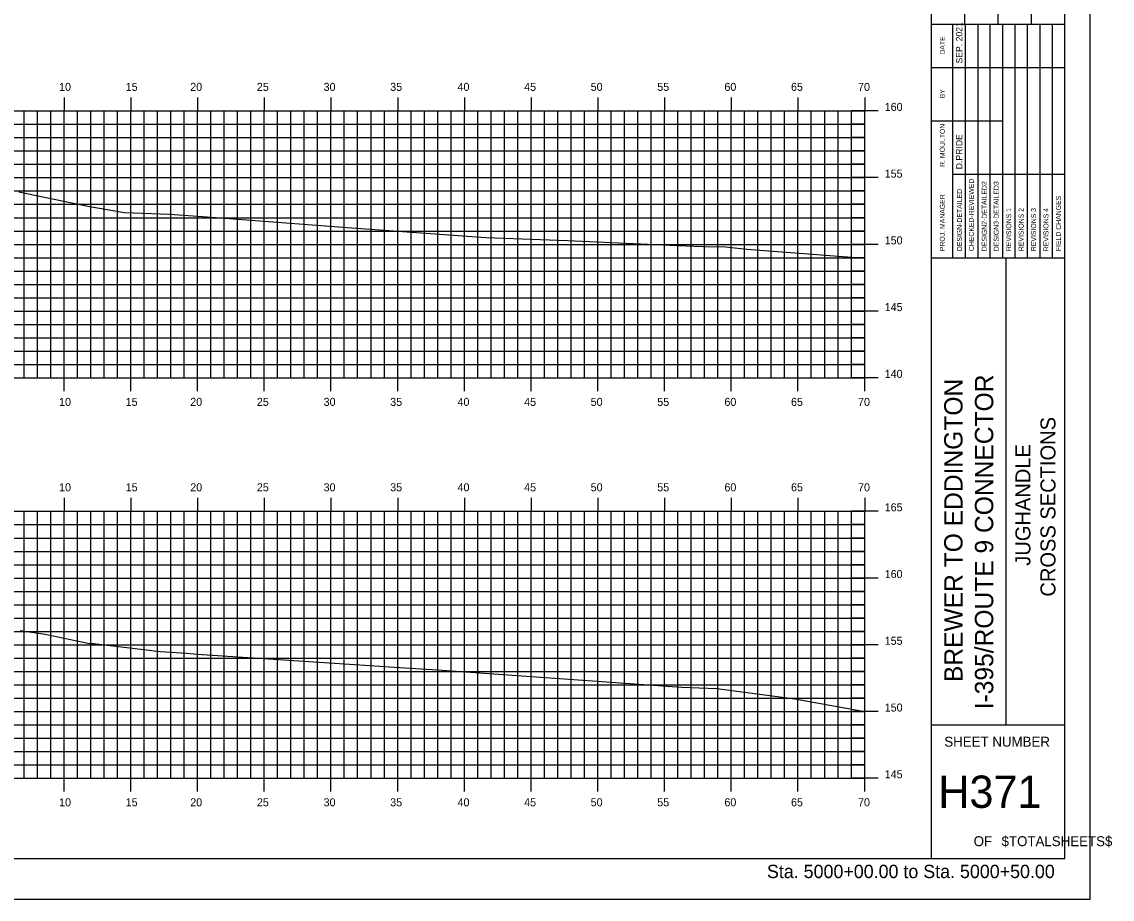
# Model space of a CAD drawing. Extents: x 850752 to 850923, y 365876 to 365986.
# Drawn here: x 850841.5 to 850923.2, y 365875.8 to 365941.5 of the extents above; entities that cross this region are included whole.
import ezdxf

# ---------------------------------------------------------------- set-up
doc = ezdxf.new("R2010")
doc.units = 0
for name, color, linetype in [('BORDER', 7, 'Continuous'), ('H_V ANNOTATION', 7, 'Continuous'), ('MAJOR', 7, 'Continuous'), ('MINOR', 7, 'Continuous'), ('PLOT BOUNDARY', 7, 'Continuous'), ('S_Roadway_Centerline', 7, 'Continuous')]:
    doc.layers.add(name, color=color, linetype=linetype)

msp = doc.modelspace()

# ---------------------------------------------------------------- linework, layer by layer
at = {"layer": 'BORDER'}
for p, q in [((850909.629, 365878.833), (850909.629, 365983.833)), ((850912.129, 365941.336), (850912.129, 365949.984)), ((850914.629, 365941.336), (850914.629, 365949.984)), ((850917.129, 365941.336), (850917.129, 365949.984)), ((850909.629, 365941.336), (850919.629, 365941.336)), ((850909.629, 365923.836), (850919.629, 365923.836)), ((850915.22, 365888.836), (850915.22, 365923.836)), ((850909.629, 365888.836), (850919.629, 365888.836))]:
    msp.add_line(p, q, dxfattribs=at)
msp.add_lwpolyline([(850759.629, 365878.833), (850919.629, 365878.833), (850919.629, 365983.833), (850759.629, 365983.833)], close=True, dxfattribs=at)
for points in [[(850911.244, 365938.086), (850911.244, 365941.336)], [(850912.176, 365923.839), (850912.176, 365941.336)], [(850913.108, 365941.336), (850913.108, 365923.839)], [(850914.04, 365923.839), (850914.04, 365941.336)], [(850914.971, 365923.839), (850914.971, 365941.336)], [(850915.903, 365923.839), (850915.903, 365941.336)], [(850916.835, 365923.839), (850916.835, 365941.336)], [(850917.767, 365923.839), (850917.767, 365941.336)], [(850918.698, 365923.839), (850918.698, 365941.336)], [(850911.245, 365923.839), (850911.245, 365940.63)], [(850909.629, 365938.086), (850919.629, 365938.086)], [(850909.629, 365934.086), (850911.245, 365934.086)], [(850911.244, 365934.086), (850914.971, 365934.086)], [(850911.244, 365930.086), (850919.629, 365930.086)]]:
    msp.add_lwpolyline(points, dxfattribs=at)
at = {"layer": 'MAJOR'}
for p, q in [((850844.629, 365935.835), (850844.629, 365934.833)), ((850849.629, 365935.835), (850849.629, 365934.833)), ((850854.629, 365935.835), (850854.629, 365934.833)), ((850859.629, 365935.835), (850859.629, 365934.833)), ((850864.629, 365935.835), (850864.629, 365934.833)), ((850869.629, 365935.835), (850869.629, 365934.833)), ((850874.629, 365935.835), (850874.629, 365934.833)), ((850879.629, 365935.835), (850879.629, 365934.833)), ((850884.629, 365935.835), (850884.629, 365934.833)), ((850889.629, 365935.835), (850889.629, 365934.833)), ((850894.629, 365935.835), (850894.629, 365934.833)), ((850899.629, 365935.835), (850899.629, 365934.833)), ((850904.629, 365935.835), (850904.629, 365934.833)), ((850764.629, 365934.833), (850904.629, 365934.833)), ((850764.629, 365934.833), (850904.629, 365934.833)), ((850844.629, 365914.833), (850844.629, 365934.833)), ((850849.629, 365914.833), (850849.629, 365934.833)), ((850854.629, 365914.833), (850854.629, 365934.833)), ((850859.629, 365914.833), (850859.629, 365934.833)), ((850864.629, 365914.833), (850864.629, 365934.833)), ((850869.629, 365914.833), (850869.629, 365934.833)), ((850874.629, 365914.833), (850874.629, 365934.833)), ((850879.629, 365914.833), (850879.629, 365934.833)), ((850884.629, 365914.833), (850884.629, 365934.833)), ((850889.629, 365914.833), (850889.629, 365934.833)), ((850894.629, 365914.833), (850894.629, 365934.833)), ((850899.629, 365914.833), (850899.629, 365934.833)), ((850905.631, 365934.833), (850903.627, 365934.833)), ((850904.629, 365914.833), (850904.629, 365934.833)), ((850904.629, 365914.833), (850904.629, 365934.833)), ((850764.629, 365929.833), (850904.629, 365929.833)), ((850905.631, 365929.833), (850903.627, 365929.833)), ((850764.629, 365924.833), (850904.629, 365924.833)), ((850905.631, 365924.833), (850903.627, 365924.833)), ((850764.629, 365919.833), (850904.629, 365919.833)), ((850905.631, 365919.833), (850903.627, 365919.833)), ((850764.629, 365914.833), (850904.629, 365914.833)), ((850764.629, 365914.833), (850904.629, 365914.833)), ((850844.629, 365913.831), (850844.629, 365914.833)), ((850849.629, 365913.831), (850849.629, 365914.833)), ((850854.629, 365913.831), (850854.629, 365914.833)), ((850859.629, 365913.831), (850859.629, 365914.833)), ((850864.629, 365913.831), (850864.629, 365914.833)), ((850869.629, 365913.831), (850869.629, 365914.833)), ((850874.629, 365913.831), (850874.629, 365914.833)), ((850879.629, 365913.831), (850879.629, 365914.833)), ((850884.629, 365913.831), (850884.629, 365914.833)), ((850889.629, 365913.831), (850889.629, 365914.833)), ((850894.629, 365913.831), (850894.629, 365914.833)), ((850899.629, 365913.831), (850899.629, 365914.833)), ((850905.631, 365914.833), (850903.627, 365914.833)), ((850904.629, 365913.831), (850904.629, 365914.833)), ((850844.629, 365905.835), (850844.629, 365904.833)), ((850849.629, 365905.835), (850849.629, 365904.833)), ((850854.629, 365905.835), (850854.629, 365904.833)), ((850859.629, 365905.835), (850859.629, 365904.833)), ((850864.629, 365905.835), (850864.629, 365904.833)), ((850869.629, 365905.835), (850869.629, 365904.833)), ((850874.629, 365905.835), (850874.629, 365904.833)), ((850879.629, 365905.835), (850879.629, 365904.833)), ((850884.629, 365905.835), (850884.629, 365904.833)), ((850889.629, 365905.835), (850889.629, 365904.833)), ((850894.629, 365905.835), (850894.629, 365904.833)), ((850899.629, 365905.835), (850899.629, 365904.833)), ((850904.629, 365905.835), (850904.629, 365904.833)), ((850764.629, 365904.833), (850904.629, 365904.833)), ((850764.629, 365904.833), (850904.629, 365904.833)), ((850844.629, 365884.833), (850844.629, 365904.833)), ((850849.629, 365884.833), (850849.629, 365904.833)), ((850854.629, 365884.833), (850854.629, 365904.833)), ((850859.629, 365884.833), (850859.629, 365904.833)), ((850864.629, 365884.833), (850864.629, 365904.833)), ((850869.629, 365884.833), (850869.629, 365904.833)), ((850874.629, 365884.833), (850874.629, 365904.833)), ((850879.629, 365884.833), (850879.629, 365904.833)), ((850884.629, 365884.833), (850884.629, 365904.833)), ((850889.629, 365884.833), (850889.629, 365904.833)), ((850894.629, 365884.833), (850894.629, 365904.833)), ((850899.629, 365884.833), (850899.629, 365904.833)), ((850905.631, 365904.833), (850903.627, 365904.833)), ((850904.629, 365884.833), (850904.629, 365904.833)), ((850904.629, 365884.833), (850904.629, 365904.833)), ((850764.629, 365899.833), (850904.629, 365899.833)), ((850905.631, 365899.833), (850903.627, 365899.833)), ((850764.629, 365894.833), (850904.629, 365894.833)), ((850905.631, 365894.833), (850903.627, 365894.833)), ((850764.629, 365889.833), (850904.629, 365889.833)), ((850905.631, 365889.833), (850903.627, 365889.833)), ((850764.629, 365884.833), (850904.629, 365884.833)), ((850764.629, 365884.833), (850904.629, 365884.833)), ((850844.629, 365883.831), (850844.629, 365884.833)), ((850849.629, 365883.831), (850849.629, 365884.833)), ((850854.629, 365883.831), (850854.629, 365884.833)), ((850859.629, 365883.831), (850859.629, 365884.833)), ((850864.629, 365883.831), (850864.629, 365884.833)), ((850869.629, 365883.831), (850869.629, 365884.833)), ((850874.629, 365883.831), (850874.629, 365884.833)), ((850879.629, 365883.831), (850879.629, 365884.833)), ((850884.629, 365883.831), (850884.629, 365884.833)), ((850889.629, 365883.831), (850889.629, 365884.833)), ((850894.629, 365883.831), (850894.629, 365884.833)), ((850899.629, 365883.831), (850899.629, 365884.833)), ((850905.631, 365884.833), (850903.627, 365884.833)), ((850904.629, 365883.831), (850904.629, 365884.833))]:
    msp.add_line(p, q, dxfattribs=at)
at = {"layer": 'MINOR'}
for p, q in [((850841.629, 365914.833), (850841.629, 365934.833)), ((850842.629, 365914.833), (850842.629, 365934.833)), ((850843.629, 365914.833), (850843.629, 365934.833)), ((850845.629, 365914.833), (850845.629, 365934.833)), ((850846.629, 365914.833), (850846.629, 365934.833)), ((850847.629, 365914.833), (850847.629, 365934.833)), ((850848.629, 365914.833), (850848.629, 365934.833)), ((850850.629, 365914.833), (850850.629, 365934.833)), ((850851.629, 365914.833), (850851.629, 365934.833)), ((850852.629, 365914.833), (850852.629, 365934.833)), ((850853.629, 365914.833), (850853.629, 365934.833)), ((850855.629, 365914.833), (850855.629, 365934.833)), ((850856.629, 365914.833), (850856.629, 365934.833)), ((850857.629, 365914.833), (850857.629, 365934.833)), ((850858.629, 365914.833), (850858.629, 365934.833)), ((850860.629, 365914.833), (850860.629, 365934.833)), ((850861.629, 365914.833), (850861.629, 365934.833)), ((850862.629, 365914.833), (850862.629, 365934.833)), ((850863.629, 365914.833), (850863.629, 365934.833)), ((850865.629, 365914.833), (850865.629, 365934.833)), ((850866.629, 365914.833), (850866.629, 365934.833)), ((850867.629, 365914.833), (850867.629, 365934.833)), ((850868.629, 365914.833), (850868.629, 365934.833)), ((850870.629, 365914.833), (850870.629, 365934.833)), ((850871.629, 365914.833), (850871.629, 365934.833)), ((850872.629, 365914.833), (850872.629, 365934.833)), ((850873.629, 365914.833), (850873.629, 365934.833)), ((850875.629, 365914.833), (850875.629, 365934.833)), ((850876.629, 365914.833), (850876.629, 365934.833)), ((850877.629, 365914.833), (850877.629, 365934.833)), ((850878.629, 365914.833), (850878.629, 365934.833)), ((850880.629, 365914.833), (850880.629, 365934.833)), ((850881.629, 365914.833), (850881.629, 365934.833)), ((850882.629, 365914.833), (850882.629, 365934.833)), ((850883.629, 365914.833), (850883.629, 365934.833)), ((850885.629, 365914.833), (850885.629, 365934.833)), ((850886.629, 365914.833), (850886.629, 365934.833)), ((850887.629, 365914.833), (850887.629, 365934.833)), ((850888.629, 365914.833), (850888.629, 365934.833)), ((850890.629, 365914.833), (850890.629, 365934.833)), ((850891.629, 365914.833), (850891.629, 365934.833)), ((850892.629, 365914.833), (850892.629, 365934.833)), ((850893.629, 365914.833), (850893.629, 365934.833)), ((850895.629, 365914.833), (850895.629, 365934.833)), ((850896.629, 365914.833), (850896.629, 365934.833)), ((850897.629, 365914.833), (850897.629, 365934.833)), ((850898.629, 365914.833), (850898.629, 365934.833)), ((850900.629, 365914.833), (850900.629, 365934.833)), ((850901.629, 365914.833), (850901.629, 365934.833)), ((850902.629, 365914.833), (850902.629, 365934.833)), ((850903.629, 365914.833), (850903.629, 365934.833)), ((850764.629, 365933.833), (850904.629, 365933.833)), ((850904.629, 365933.833), (850903.627, 365933.833)), ((850764.629, 365932.833), (850904.629, 365932.833)), ((850904.629, 365932.833), (850903.627, 365932.833)), ((850764.629, 365931.833), (850904.629, 365931.833)), ((850904.629, 365931.833), (850903.627, 365931.833)), ((850764.629, 365930.833), (850904.629, 365930.833)), ((850904.629, 365930.833), (850903.627, 365930.833)), ((850764.629, 365928.833), (850904.629, 365928.833)), ((850904.629, 365928.833), (850903.627, 365928.833)), ((850764.629, 365927.833), (850904.629, 365927.833)), ((850904.629, 365927.833), (850903.627, 365927.833)), ((850764.629, 365926.833), (850904.629, 365926.833)), ((850904.629, 365926.833), (850903.627, 365926.833)), ((850764.629, 365925.833), (850904.629, 365925.833)), ((850904.629, 365925.833), (850903.627, 365925.833)), ((850764.629, 365923.833), (850904.629, 365923.833)), ((850904.629, 365923.833), (850903.627, 365923.833)), ((850764.629, 365922.833), (850904.629, 365922.833)), ((850904.629, 365922.833), (850903.627, 365922.833)), ((850764.629, 365921.833), (850904.629, 365921.833)), ((850904.629, 365921.833), (850903.627, 365921.833)), ((850764.629, 365920.833), (850904.629, 365920.833)), ((850904.629, 365920.833), (850903.627, 365920.833)), ((850764.629, 365918.833), (850904.629, 365918.833)), ((850904.629, 365918.833), (850903.627, 365918.833)), ((850764.629, 365917.833), (850904.629, 365917.833)), ((850904.629, 365917.833), (850903.627, 365917.833)), ((850764.629, 365916.833), (850904.629, 365916.833)), ((850904.629, 365916.833), (850903.627, 365916.833)), ((850764.629, 365915.833), (850904.629, 365915.833)), ((850904.629, 365915.833), (850903.627, 365915.833)), ((850841.629, 365884.833), (850841.629, 365904.833)), ((850842.629, 365884.833), (850842.629, 365904.833)), ((850843.629, 365884.833), (850843.629, 365904.833)), ((850845.629, 365884.833), (850845.629, 365904.833)), ((850846.629, 365884.833), (850846.629, 365904.833)), ((850847.629, 365884.833), (850847.629, 365904.833)), ((850848.629, 365884.833), (850848.629, 365904.833)), ((850850.629, 365884.833), (850850.629, 365904.833)), ((850851.629, 365884.833), (850851.629, 365904.833)), ((850852.629, 365884.833), (850852.629, 365904.833)), ((850853.629, 365884.833), (850853.629, 365904.833)), ((850855.629, 365884.833), (850855.629, 365904.833)), ((850856.629, 365884.833), (850856.629, 365904.833)), ((850857.629, 365884.833), (850857.629, 365904.833)), ((850858.629, 365884.833), (850858.629, 365904.833)), ((850860.629, 365884.833), (850860.629, 365904.833)), ((850861.629, 365884.833), (850861.629, 365904.833)), ((850862.629, 365884.833), (850862.629, 365904.833)), ((850863.629, 365884.833), (850863.629, 365904.833)), ((850865.629, 365884.833), (850865.629, 365904.833)), ((850866.629, 365884.833), (850866.629, 365904.833)), ((850867.629, 365884.833), (850867.629, 365904.833)), ((850868.629, 365884.833), (850868.629, 365904.833)), ((850870.629, 365884.833), (850870.629, 365904.833)), ((850871.629, 365884.833), (850871.629, 365904.833)), ((850872.629, 365884.833), (850872.629, 365904.833)), ((850873.629, 365884.833), (850873.629, 365904.833)), ((850875.629, 365884.833), (850875.629, 365904.833)), ((850876.629, 365884.833), (850876.629, 365904.833)), ((850877.629, 365884.833), (850877.629, 365904.833)), ((850878.629, 365884.833), (850878.629, 365904.833)), ((850880.629, 365884.833), (850880.629, 365904.833)), ((850881.629, 365884.833), (850881.629, 365904.833)), ((850882.629, 365884.833), (850882.629, 365904.833)), ((850883.629, 365884.833), (850883.629, 365904.833)), ((850885.629, 365884.833), (850885.629, 365904.833)), ((850886.629, 365884.833), (850886.629, 365904.833)), ((850887.629, 365884.833), (850887.629, 365904.833)), ((850888.629, 365884.833), (850888.629, 365904.833)), ((850890.629, 365884.833), (850890.629, 365904.833)), ((850891.629, 365884.833), (850891.629, 365904.833)), ((850892.629, 365884.833), (850892.629, 365904.833)), ((850893.629, 365884.833), (850893.629, 365904.833)), ((850895.629, 365884.833), (850895.629, 365904.833)), ((850896.629, 365884.833), (850896.629, 365904.833)), ((850897.629, 365884.833), (850897.629, 365904.833)), ((850898.629, 365884.833), (850898.629, 365904.833)), ((850900.629, 365884.833), (850900.629, 365904.833)), ((850901.629, 365884.833), (850901.629, 365904.833)), ((850902.629, 365884.833), (850902.629, 365904.833)), ((850903.629, 365884.833), (850903.629, 365904.833)), ((850764.629, 365903.833), (850904.629, 365903.833)), ((850904.629, 365903.833), (850903.627, 365903.833)), ((850764.629, 365902.833), (850904.629, 365902.833)), ((850904.629, 365902.833), (850903.627, 365902.833)), ((850764.629, 365901.833), (850904.629, 365901.833)), ((850904.629, 365901.833), (850903.627, 365901.833)), ((850764.629, 365900.833), (850904.629, 365900.833)), ((850904.629, 365900.833), (850903.627, 365900.833)), ((850764.629, 365898.833), (850904.629, 365898.833)), ((850904.629, 365898.833), (850903.627, 365898.833)), ((850764.629, 365897.833), (850904.629, 365897.833)), ((850904.629, 365897.833), (850903.627, 365897.833)), ((850764.629, 365896.833), (850904.629, 365896.833)), ((850904.629, 365896.833), (850903.627, 365896.833)), ((850764.629, 365895.833), (850904.629, 365895.833)), ((850904.629, 365895.833), (850903.627, 365895.833)), ((850764.629, 365893.833), (850904.629, 365893.833)), ((850904.629, 365893.833), (850903.627, 365893.833)), ((850764.629, 365892.833), (850904.629, 365892.833)), ((850904.629, 365892.833), (850903.627, 365892.833)), ((850764.629, 365891.833), (850904.629, 365891.833)), ((850904.629, 365891.833), (850903.627, 365891.833)), ((850764.629, 365890.833), (850904.629, 365890.833)), ((850904.629, 365890.833), (850903.627, 365890.833)), ((850764.629, 365888.833), (850904.629, 365888.833)), ((850904.629, 365888.833), (850903.627, 365888.833)), ((850764.629, 365887.833), (850904.629, 365887.833)), ((850904.629, 365887.833), (850903.627, 365887.833)), ((850764.629, 365886.833), (850904.629, 365886.833)), ((850904.629, 365886.833), (850903.627, 365886.833)), ((850764.629, 365885.833), (850904.629, 365885.833)), ((850904.629, 365885.833), (850903.627, 365885.833))]:
    msp.add_line(p, q, dxfattribs=at)
at = {"layer": 'PLOT BOUNDARY'}
msp.add_lwpolyline([(850751.536, 365875.774), (850921.536, 365875.774), (850921.536, 365985.774), (850751.536, 365985.774)], close=True, dxfattribs=at)
at = {"layer": 'S_Roadway_Centerline'}
for points in [[(850841.227, 365928.777), (850846.397, 365927.684), (850849.164, 365927.229), (850852.535, 365927.106), (850855.355, 365926.886), (850865.835, 365926.099), (850876.225, 365925.344), (850882.365, 365925.13), (850890.598, 365924.744), (850892.525, 365924.67), (850894.222, 365924.645), (850895.8, 365924.468), (850904.629, 365923.79)], [(850841.333, 365895.907), (850843.206, 365895.619), (850846.528, 365894.918), (850846.835, 365894.927), (850851.819, 365894.339), (850853.819, 365894.195), (850854.606, 365894.121), (850867.529, 365893.285), (850869.759, 365893.126), (850872.618, 365892.955), (850890.908, 365891.646), (850893.54, 365891.552), (850899.388, 365890.781), (850904.629, 365889.833)]]:
    msp.add_lwpolyline(points, dxfattribs=at)

# ---------------------------------------------------------------- texts
at = {"layer": 'BORDER'}
for s, height, p in [('SEP. 2021', 0.4845, (850911.952, 365938.382)), ('DATE', 0.3714, (850910.633, 365939.042)), ('BY', 0.3714, (850910.633, 365935.771)), ('R. MOULTON', 0.3727, (850910.633, 365930.639)), ('D.PRIDE', 0.4845, (850911.952, 365930.459)), ('DESIGN-DETAILED', 0.37275, (850911.916, 365924.324)), ('CHECKED-REVIEWED', 0.37275, (850912.81, 365924.324)), ('DESIGN2-DETAILED2', 0.37275, (850913.779, 365924.324)), ('DESIGN3-DETAILED3', 0.37275, (850914.673, 365924.324)), ('PROJ. MANAGER', 0.37275, (850910.633, 365924.324)), ('FIELD CHANGES', 0.37275, (850919.332, 365924.324)), ('REVISIONS 1', 0.37275, (850915.605, 365924.324)), ('REVISIONS 2', 0.37275, (850916.537, 365924.324)), ('REVISIONS 3', 0.37275, (850917.468, 365924.324)), ('REVISIONS 4', 0.37275, (850918.4, 365924.324)), ('I-395/ROUTE 9 CONNECTOR', 1.37787, (850914.264, 365889.998)), ('BREWER TO EDDINGTON', 1.37787, (850911.963, 365892.038)), ('CROSS SECTIONS', 1.125, (850918.926, 365898.444)), ('JUGHANDLE', 1.125, (850917.048, 365900.756))]:
    msp.add_text(s, height=height, rotation=90, dxfattribs=at).set_placement(p)
for s, height, p in [('SHEET NUMBER', 0.74527, (850910.594, 365887.2)), ('H371', 2.4194, (850910.144, 365882.616)), ('$TOTALSHEETS$', 0.74527, (850914.885, 365879.746)), ('OF', 0.7453, (850912.796, 365879.746))]:
    msp.add_text(s, height=height, dxfattribs=at).set_placement(p)
at = {"layer": 'H_V ANNOTATION'}
for s, height, p in [('10', 0.6, (850844.254, 365936.333)), ('15', 0.6, (850849.246, 365936.333)), ('20', 0.6, (850854.083, 365936.333)), ('25', 0.6, (850859.075, 365936.333)), ('30', 0.6, (850864.077, 365936.333)), ('35', 0.6, (850869.069, 365936.333)), ('40', 0.6, (850874.115, 365936.333)), ('45', 0.6, (850879.107, 365936.333)), ('50', 0.6, (850884.093, 365936.333)), ('55', 0.6, (850889.085, 365936.333)), ('60', 0.6, (850894.115, 365936.333)), ('65', 0.6, (850899.107, 365936.333)), ('70', 0.6, (850904.131, 365936.333)), ('160', 0.6, (850906.129, 365934.833)), ('155', 0.6, (850906.129, 365929.833)), ('150', 0.6, (850906.129, 365924.833)), ('145', 0.6, (850906.129, 365919.833)), ('140', 0.6, (850906.129, 365914.833)), ('10', 0.6, (850844.254, 365912.733)), ('15', 0.6, (850849.246, 365912.733)), ('20', 0.6, (850854.083, 365912.733)), ('25', 0.6, (850859.075, 365912.733)), ('30', 0.6, (850864.077, 365912.733)), ('35', 0.6, (850869.069, 365912.733)), ('40', 0.6, (850874.115, 365912.733)), ('45', 0.6, (850879.107, 365912.733)), ('50', 0.6, (850884.093, 365912.733)), ('55', 0.6, (850889.085, 365912.733)), ('60', 0.6, (850894.115, 365912.733)), ('65', 0.6, (850899.107, 365912.733)), ('70', 0.6, (850904.131, 365912.733)), ('10', 0.6, (850844.254, 365906.333)), ('15', 0.6, (850849.246, 365906.333)), ('20', 0.6, (850854.083, 365906.333)), ('25', 0.6, (850859.075, 365906.333)), ('30', 0.6, (850864.077, 365906.333)), ('35', 0.6, (850869.069, 365906.333)), ('40', 0.6, (850874.115, 365906.333)), ('45', 0.6, (850879.107, 365906.333)), ('50', 0.6, (850884.093, 365906.333)), ('55', 0.6, (850889.085, 365906.333)), ('60', 0.6, (850894.115, 365906.333)), ('65', 0.6, (850899.107, 365906.333)), ('70', 0.6, (850904.131, 365906.333)), ('165', 0.6, (850906.129, 365904.833)), ('160', 0.6, (850906.129, 365899.833)), ('155', 0.6, (850906.129, 365894.833)), ('150', 0.6, (850906.129, 365889.833)), ('145', 0.6, (850906.129, 365884.833)), ('10', 0.6, (850844.254, 365882.733)), ('15', 0.6, (850849.246, 365882.733)), ('20', 0.6, (850854.083, 365882.733)), ('25', 0.6, (850859.075, 365882.733)), ('30', 0.6, (850864.077, 365882.733)), ('35', 0.6, (850869.069, 365882.733)), ('40', 0.6, (850874.115, 365882.733)), ('45', 0.6, (850879.107, 365882.733)), ('50', 0.6, (850884.093, 365882.733)), ('55', 0.6, (850889.085, 365882.733)), ('60', 0.6, (850894.115, 365882.733)), ('65', 0.6, (850899.107, 365882.733)), ('70', 0.6, (850904.131, 365882.733)), ('Sta. 5000+00.00 to Sta. 5000+50.00', 1.0002, (850897.305, 365877.353))]:
    msp.add_text(s, height=height, dxfattribs=at).set_placement(p)

doc.saveas('drawing.dxf')
